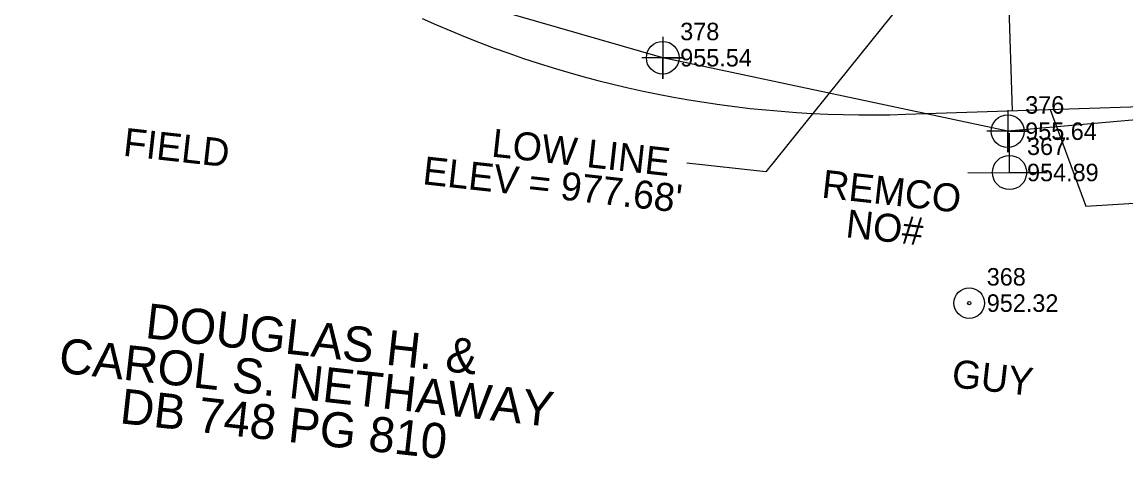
# Model space of a CAD drawing. Extents: x 1150279 to 1151282, y 655434 to 657999.
# Drawn here: x 1150895 to 1151052.7, y 656992.9 to 657055.2 of the extents above; entities that cross this region are included whole.
import ezdxf

# ---------------------------------------------------------------- set-up
doc = ezdxf.new("R2010")
doc.units = 0
for name, color, linetype in [('Exist Other Culture Anchor (Guy Wire) CELL', 7, 'Continuous'), ('Exist Other Culture Anchor (Guy Wire) Cogo Elevation', 7, 'Continuous'), ('Exist Other Culture Anchor (Guy Wire) Cogo Number', 7, 'Continuous'), ('Exist Other Culture Fence Line', 7, 'Continuous'), ('Exist Other Culture Fence Line Cogo Elevation', 7, 'Continuous'), ('Exist Other Culture Fence Line Cogo Number', 7, 'Continuous'), ('Exist Other Culture Fence Line Cogo Point CELL', 7, 'Continuous'), ('Exist Property Deed Book Text', 7, 'Continuous'), ('Exist Property Owner Text', 7, 'Continuous'), ('Exist Right of Way Line', 7, 'Continuous'), ('Exist Right of Way Line Leader', 7, 'Continuous'), ('Exist Right of Way Width CELL', 7, 'Continuous'), ('Exist Utilities Other Located Object Leader', 7, 'Continuous'), ('Exist Utilities Other Located Object Text', 7, 'Continuous'), ('Exist Utilities Power Joint Use Telephone CELL', 7, 'Continuous'), ('Exist Utilities Power Joint Use Telephone Cogo Elevation', 7, 'Continuous'), ('Exist Utilities Power Joint Use Telephone Cogo Number', 7, 'Continuous'), ('Exist Utilities Power Joint Use Telephone Text', 7, 'Continuous'), ('Exist Vegetation Woods Line Text', 7, 'Continuous')]:
    doc.layers.add(name, color=color, linetype=linetype)

msp = doc.modelspace()

# ---------------------------------------------------------------- linework, layer by layer
at = {"layer": 'Exist Other Culture Anchor (Guy Wire) CELL'}
for radius in [2.18, 0.24]:
    msp.add_circle((1151030.3, 657015.11), radius, dxfattribs=at)
at = {"layer": 'Exist Other Culture Fence Line'}
msp.add_lwpolyline([(1151064.38, 657042.2), (1151035.79, 657039.66), (1150986.53, 657050.15), (1150941.42, 657063.2), (1150898.39, 657078.65), (1150854.86, 657094.99), (1150825.03, 657100.53), (1150812.46, 657091.59), (1150835.17, 657043.74), (1150852.72, 657007.43)], dxfattribs=at)
at = {"layer": 'Exist Other Culture Fence Line Cogo Point CELL'}
for points in [[(1150986.53, 657053.15), (1150986.53, 657047.15), (1150986.53, 657050.15), (1150989.53, 657050.15), (1150983.53, 657050.15)], [(1151035.79, 657042.66), (1151035.79, 657036.66), (1151035.79, 657039.66), (1151038.79, 657039.66), (1151032.79, 657039.66)]]:
    msp.add_lwpolyline(points, dxfattribs=at)
for centre in [(1150986.53, 657050.15), (1151035.79, 657039.66)]:
    msp.add_circle(centre, 2.34, dxfattribs=at)
at = {"layer": 'Exist Right of Way Line'}
msp.add_line((1151021.2, 657042.08), (1151060.89, 657043.41), dxfattribs=at)
msp.add_arc((1151016.01, 657196.99), 155, 245.6804, 271.9187, dxfattribs=at)
at = {"layer": 'Exist Right of Way Line Leader'}
msp.add_lwpolyline([(1151041.84, 657042.77), (1151046.96, 657028.97), (1151056.17, 657029.54)], dxfattribs=at)
at = {"layer": 'Exist Right of Way Width CELL'}
msp.add_line((1151036.48, 657042.59), (1151035.67, 657066.81), dxfattribs=at)
at = {"layer": 'Exist Utilities Other Located Object Leader'}
msp.add_lwpolyline([(1151026.43, 657065.18), (1151001.23, 657033.86), (1150989.95, 657035.11)], dxfattribs=at)
at = {"layer": 'Exist Utilities Power Joint Use Telephone CELL'}
msp.add_line((1151036.05, 657033.76), (1151036.05, 657033.76), dxfattribs=at)
msp.add_lwpolyline([(1151030.11, 657033.76), (1151041.45, 657033.72), (1151036.05, 657033.74), (1151036.05, 657039.38)], dxfattribs=at)
msp.add_circle((1151036.05, 657033.76), 2.45, dxfattribs=at)

# ---------------------------------------------------------------- texts
at = {"layer": 'Exist Other Culture Anchor (Guy Wire) Cogo Elevation'}
msp.add_text('952.32', height=2.5, dxfattribs=at).set_placement((1151032.8, 657013.86))
at = {"layer": 'Exist Other Culture Anchor (Guy Wire) Cogo Number'}
msp.add_text('368', height=2.5, dxfattribs=at).set_placement((1151032.8, 657017.61))
at = {"layer": 'Exist Other Culture Fence Line Cogo Elevation'}
for s, p in [('955.54', (1150989.03, 657048.9)), ('955.64', (1151038.29, 657038.41))]:
    msp.add_text(s, height=2.5, dxfattribs=at).set_placement(p)
at = {"layer": 'Exist Other Culture Fence Line Cogo Number'}
for s, p in [('378', (1150989.03, 657052.65)), ('376', (1151038.29, 657042.16))]:
    msp.add_text(s, height=2.5, dxfattribs=at).set_placement(p)
at = {"layer": 'Exist Property Deed Book Text'}
msp.add_text('DB 748 PG 810', height=5, rotation=353.6867, dxfattribs=at).set_placement((1150908.88, 656997.96))
at = {"layer": 'Exist Property Owner Text'}
for s, p in [('DOUGLAS H. &', (1150912.52, 657010.13)), ('CAROL S. NETHAWAY', (1150900.13, 657005.21))]:
    msp.add_text(s, height=5, rotation=353.6867, dxfattribs=at).set_placement(p)
at = {"layer": 'Exist Utilities Other Located Object Text'}
for s, p in [('LOW LINE', (1150961.96, 657036.05)), ("ELEV = 977.68'", (1150952.13, 657032.1))]:
    msp.add_text(s, height=4, rotation=353.6867, dxfattribs=at).set_placement(p)
at = {"layer": 'Exist Utilities Power Joint Use Telephone Cogo Elevation'}
msp.add_text('954.89', height=2.5, dxfattribs=at).set_placement((1151038.55, 657032.51))
at = {"layer": 'Exist Utilities Power Joint Use Telephone Cogo Number'}
msp.add_text('367', height=2.5, dxfattribs=at).set_placement((1151038.55, 657036.26))
at = {"layer": 'Exist Utilities Power Joint Use Telephone Text'}
for s, p in [('REMCO', (1151009.11, 657030.19)), ('NO#', (1151012.54, 657024.53)), ('GUY', (1151027.67, 657003.12))]:
    msp.add_text(s, height=4, rotation=353.6867, dxfattribs=at).set_placement(p)
at = {"layer": 'Exist Vegetation Woods Line Text'}
msp.add_text('FIELD', height=4, rotation=353.6867, dxfattribs=at).set_placement((1150909.37, 657036.17))

doc.saveas('drawing.dxf')
